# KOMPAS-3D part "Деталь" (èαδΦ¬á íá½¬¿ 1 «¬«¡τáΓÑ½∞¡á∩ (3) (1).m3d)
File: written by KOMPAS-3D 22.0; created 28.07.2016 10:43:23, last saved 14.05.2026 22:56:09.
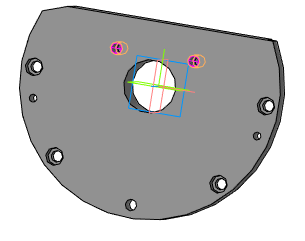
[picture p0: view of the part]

Document properties: Полное имя файла: E:\test_kompas\all_v20\Крышка балки 1 окончательная (3) (1).m3d

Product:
- Part/product: Деталь
    Масса: 9.688835
- Part/product: Деталь  | designation 01
    Масса: 9.688835

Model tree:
1. Эскиз:1
2. Операция выдавливания:1
     Расстояние 1 = 40
3. Эскиз:2  (with: Операция выдавливания:1)
4. Элемент выдавливания:2
     Расстояние 2 = 20
5. Эскиз:13  (with: Операция выдавливания:1)
6. Элемент выдавливания:5
     Расстояние 2 = 40
7. Эскиз:14  (with: Операция выдавливания:1)
8. Эскиз:15  (with: Операция выдавливания:1, Элемент выдавливания:2)
9. Элемент выдавливания:6
     Расстояние 2 = 40
10. Эскиз:16  (with: Операция выдавливания:1, Элемент выдавливания:2)
11. Элемент выдавливания:7
     Расстояние 2 = 11
12. Отверстие:3  (with: Операция выдавливания:1)  (labels: M12)
     Глубина выреза = 30; Диаметр отверстия = 10.1056; Угол конуса дна = 118; Расстояние 1 = 31; Расстояние 2 = 46.4075
13. M12  (with: Отверстие:3, Операция выдавливания:1)  (labels: M12; cil0_24705-2004 coarse)
     Длина резьбы = 25; Шаг резьбы = 1.75; Номинальный диаметр резьбы = 12
14. Отверстие:4  (with: Операция выдавливания:1, M12)  (labels: M12; cil0_24705-2004 coarse)
     Глубина выреза = 30; Диаметр отверстия = 10.1056; Угол конуса дна = 118; Расстояние 1 = 31; Расстояние 2 = 70.8326; Длина резьбы = 25; Шаг резьбы = 1.75; Номинальный диаметр резьбы = 12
